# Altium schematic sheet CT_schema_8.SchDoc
size 297 x 239 mm
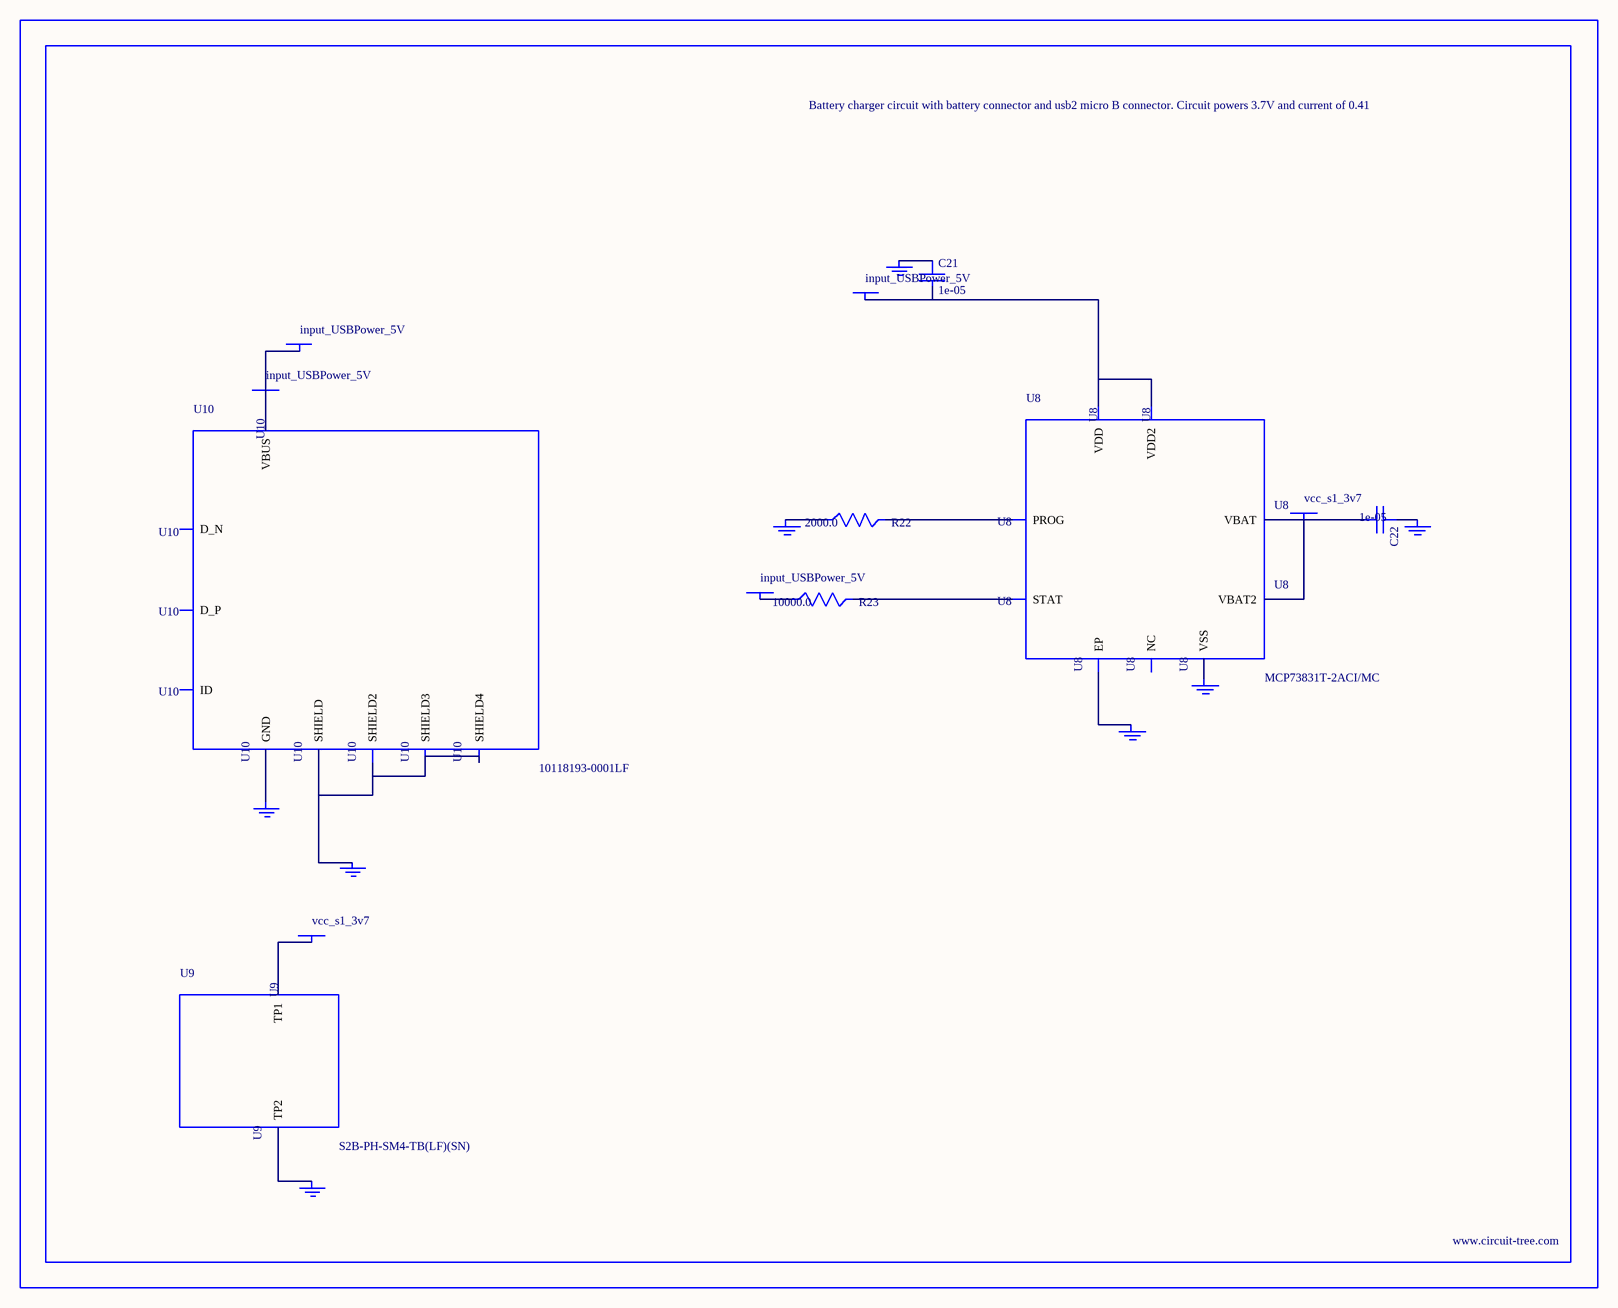
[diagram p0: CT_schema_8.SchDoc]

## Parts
BORDER7  (no value)
C21  1e-05  [C1206]
C22  1e-05  [C1206]
GND_INSTANCE_7_0  (no value)
GND_INSTANCE_7_1  (no value)
GND_INSTANCE_7_2  (no value)
GND_INSTANCE_7_3  (no value)
GND_INSTANCE_7_4  (no value)
GND_INSTANCE_7_5  (no value)
GND_INSTANCE_7_6  (no value)
GND_INSTANCE_7_7  (no value)
POWER_INSTANCE_7_0  input_USBPower_5V
POWER_INSTANCE_7_1  input_USBPower_5V
POWER_INSTANCE_7_2  vcc_s1_3v7
POWER_INSTANCE_7_3  vcc_s1_3v7
POWER_INSTANCE_7_4  input_USBPower_5V
POWER_INSTANCE_7_5  input_USBPower_5V
R22  2000.0  [R0603]
R23  10000.0  [R0603]
U8  MCP73831T-2ACI/MC  [DFN8_2X3MC]
U9  S2B-PH-SM4-TB(LF)(SN)  [JST-2-SMD]
U10  10118193-0001LF  [FCI_10118193-0001LF]

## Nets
NetC21_1: C21.1 GND_INSTANCE_7_0.0(GND)
NetC21_2: C21.2 POWER_INSTANCE_7_0.0(PWR) U8.1(VDD) U8.2(VDD2)
NetC22_1: C22.1 GND_INSTANCE_7_1.0(GND)
NetC22_2: C22.2 POWER_INSTANCE_7_2.0(PWR) U8.3(VBAT) U8.4(VBAT2)
NetGND_INSTANCE_7_2_0: GND_INSTANCE_7_2.0(GND) R22.1
NetGND_INSTANCE_7_3_0: GND_INSTANCE_7_3.0(GND) U8.9(EP)
NetGND_INSTANCE_7_4_0: GND_INSTANCE_7_4.0(GND) U8.6(VSS)
NetGND_INSTANCE_7_5_0: GND_INSTANCE_7_5.0(GND) U9.2(TP2)
NetGND_INSTANCE_7_6_0: GND_INSTANCE_7_6.0(GND) U10.6(SHIELD) U10.7(SHIELD2) U10.8(SHIELD3) U10.9(SHIELD4)
NetGND_INSTANCE_7_7_0: GND_INSTANCE_7_7.0(GND) U10.5(GND)
NetPOWER_INSTANCE_7_1_0: POWER_INSTANCE_7_1.0(PWR) R23.1
NetPOWER_INSTANCE_7_3_0: POWER_INSTANCE_7_3.0(PWR) U9.1(TP1)
NetPOWER_INSTANCE_7_4_0: POWER_INSTANCE_7_4.0(PWR) POWER_INSTANCE_7_5.0(PWR) U10.1(VBUS)
NetR22_2: R22.2 U8.8(PROG)
NetR23_2: R23.2 U8.5(STAT)

Not connected (* = marked no-connect by the designer): U8 7(NC); U10 2(D_N) 3(D_P) 4(ID)

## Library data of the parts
BORDER7 = BORDER_PAGE7
C21 C22 = C1206C106K3RACTU
GND_INSTANCE_7_0-GND_INSTANCE_7_7 = GND
POWER_INSTANCE_7_0-POWER_INSTANCE_7_5 = PWR
R22 = RC0603JR-072KL
R23 = RC0603JR-0710KL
